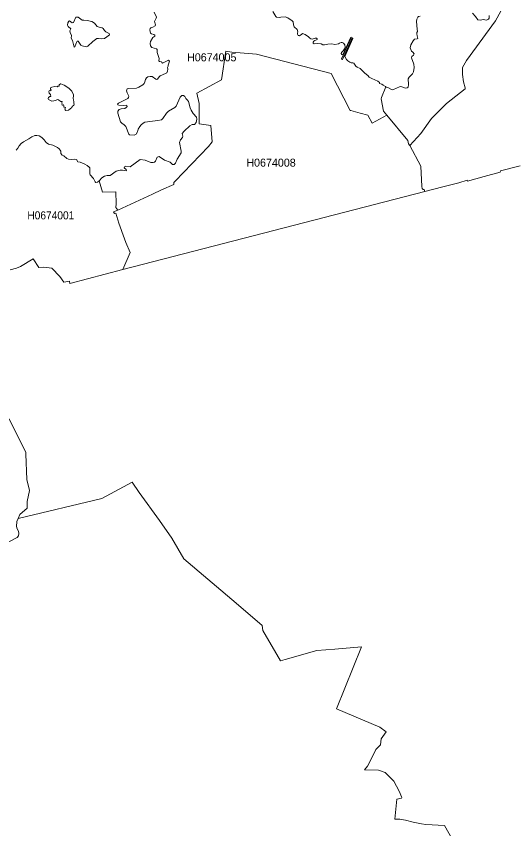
# Model space of a CAD drawing. Extents: x 369010 to 739155, y 6377141 to 6616555.
# Drawn here: x 475314 to 481540, y 6526211 to 6536366 of the extents above; entities that cross this region are included whole.
import ezdxf
from ezdxf.enums import TextEntityAlignment as Align

# ---------------------------------------------------------------- set-up
doc = ezdxf.new("R2010")
doc.units = 0
doc.header["$LTSCALE"] = 40
doc.layers.add('1', color=7, linetype='Continuous', lineweight=13)
doc.layers.add('2', color=7, linetype='Continuous')

msp = doc.modelspace()

# ---------------------------------------------------------------- linework, layer by layer
at = {"layer": '1'}
for points in [[(476200.86, 6536311.81), (476159.48, 6536316.77), (476134.65, 6536315.62), (476105.19, 6536341.6), (476084.84, 6536355.17), (476056.54, 6536355.17), (476028.4, 6536289.63), (476013.67, 6536284), (475978.58, 6536307.67), (475968.49, 6536305.35), (475956.08, 6536285), (475954.92, 6536253.39), (475961.7, 6536237.66), (475994.47, 6536208.2), (475983.22, 6536185.53), (475987.69, 6536164.01), (476002.42, 6536126.78), (475998.94, 6536092.85), (476014.83, 6536062.39), (476037.34, 6535980.97), (476044.12, 6535984.28), (476050.91, 6535994.54), (476064.48, 6536037.4), (476075.9, 6536056.77), (476088.31, 6536055.61), (476119.92, 6536004.63), (476135.65, 6535997.85), (476188.77, 6535985.44), (476209.13, 6535993.38), (476267.89, 6536049.98), (476318.86, 6536088.38), (476340.21, 6536089.54), (476376.46, 6536083.74), (476413.69, 6536088.38), (476446.46, 6536108.74), (476478.08, 6536135.88), (476474.77, 6536151.6), (476430.74, 6536171.96), (476416.01, 6536187.85), (476400.12, 6536212.67), (476385.56, 6536220.62), (476361.73, 6536224.09), (476325.65, 6536237.66), (476289.4, 6536281.69), (476257.79, 6536300.89)], [(476581.52, 6533944.27), (476529.71, 6533920.11), (476539.15, 6533899.42), (476556.36, 6533906.71), (476596.58, 6533780.59), (476666.92, 6533583.48), (476681.98, 6533539.78), (476735.6, 6533414.5), (476646.56, 6533201), (480416.24, 6534176.97), (480410.12, 6534198.99), (480397.21, 6534199.65), (480383.8, 6534211.89), (480378.84, 6534236.39), (480365.43, 6534492.75), (480228.89, 6534750.28), (480211.85, 6534769.97), (480204.4, 6534812.84), (479942.74, 6535127.96), (479757.87, 6535030.81), (479706.4, 6535130.28), (479607.59, 6535154.94), (479492.9, 6535186.55), (479483.63, 6535188.7), (479247.62, 6535651.78), (478314.84, 6535894.41), (478006.5, 6535915.43), (477929.38, 6535930.98), (477877.25, 6535570.02), (477569.08, 6535403.52), (477598.21, 6535273.77), (477598.37, 6535022.53), (477745.01, 6534999.69), (477759.74, 6534797.61), (477712.57, 6534740.35), (477296.33, 6534304.74), (477282.59, 6534287.53), (477280.44, 6534277.77), (477281.93, 6534264.86), (477127.02, 6534196.67), (477013.15, 6534143.04)], [(475959.39, 6535476.84), (475910.4, 6535505.31), (475868.86, 6535520.2), (475864.55, 6535520.04), (475850.15, 6535508.29), (475847.67, 6535493.06), (475831.78, 6535493.72), (475822.68, 6535485.78), (475793.55, 6535487.76), (475757.8, 6535481.97), (475742.08, 6535470.55), (475739.76, 6535461.45), (475740.59, 6535454), (475751.35, 6535441.26), (475745.72, 6535434.31), (475730.99, 6535436.62), (475725.53, 6535432.98), (475720.89, 6535423.71), (475724.7, 6535406.34), (475740.09, 6535389.29), (475743.9, 6535363.14), (475732.31, 6535361.82), (475716.1, 6535351.39), (475711.63, 6535343.28), (475711.46, 6535333.02), (475716.43, 6535325.57), (475757.8, 6535306.54), (475783.29, 6535307.7), (475800.5, 6535312), (475833.44, 6535326.4), (475868.36, 6535300.75), (475886.9, 6535299.92), (475888.22, 6535297.27), (475881.43, 6535288.17), (475880.77, 6535280.06), (475885.9, 6535270.29), (475883.75, 6535262.35), (475886.07, 6535256.89), (475891.86, 6535254.07), (475897.98, 6535258.38), (475902.45, 6535257.71), (475906.92, 6535251.76), (475908.25, 6535235.7), (475913.54, 6535229.08), (475930.42, 6535224.45), (475921.65, 6535206.74), (475923.8, 6535197.31), (475931.75, 6535190.02), (475967.33, 6535193.66), (476007.05, 6535223.79), (476013.67, 6535236.7), (476033.53, 6535252.91), (476038.5, 6535262.35), (476033.53, 6535282.37), (476033.7, 6535302.4), (476027.08, 6535317.79), (476024.43, 6535343.61), (476029.56, 6535371.75), (476027.08, 6535384.82), (476007.55, 6535428.68), (475976.1, 6535463.27)]]:
    msp.add_lwpolyline(points, close=True, dxfattribs=at)
for points in [[(477037.31, 6536418.89), (477065.12, 6536354.51), (477061.97, 6536342.59), (477040.29, 6536301.55), (477052.71, 6536260.01), (477047.41, 6536248.09), (477018.78, 6536227.9), (476993.12, 6536220.78), (476986.5, 6536214.66), (476982.53, 6536196.95), (476991.3, 6536154.58), (477003.22, 6536147.63), (477030.69, 6536138.69), (477042.61, 6536130.75), (477044.26, 6536118.5), (477019.6, 6536099.14), (476991.3, 6536051.8), (476986.01, 6536027.14), (476990.97, 6535995.37), (477008.52, 6535976.5), (477063.63, 6535957.47), (477072.07, 6535949.52), (477073.56, 6535914.6), (477099.87, 6535839.63), (477095.57, 6535810.17), (477102.19, 6535802.22), (477129, 6535797.75), (477132.64, 6535787.16), (477139.59, 6535780.54), (477215.89, 6535815.79), (477225.66, 6535804.7), (477210.27, 6535755.88), (477209.77, 6535740.82), (477202.32, 6535726.26), (477207.95, 6535705.57), (477204.47, 6535678.59), (477193.38, 6535658.4), (477179.32, 6535649.13), (477111.46, 6535623.15), (477096.89, 6535609.91), (477079.19, 6535578.96), (477069.92, 6535574.99), (477057.17, 6535579.45), (477010.01, 6535611.23), (476987, 6535615.2), (476955.22, 6535608.91), (476938.18, 6535596.67), (476926.26, 6535574.99), (476921.3, 6535545.36), (476909.88, 6535525.67), (476894.32, 6535510.77), (476846.16, 6535480.48), (476814.05, 6535465.92)], [(478833.69, 6536125.29), (478826.91, 6536140.68), (478826.08, 6536153.92), (478830.22, 6536169.48), (478823.93, 6536199.76), (478785.2, 6536233.53), (478776.93, 6536258.52), (478772.79, 6536296.75), (478761.2, 6536309.66), (478703.77, 6536346.23), (478673.82, 6536357.49), (478619.37, 6536356.66), (478597.69, 6536352.03), (478564.42, 6536355.83), (478553.66, 6536362.12), (478519.9, 6536425.51)], [(480289.3, 6536078.45), (480271.1, 6536057.1), (480242.3, 6536009.27), (480233.2, 6535970.71), (480248.92, 6535931.15), (480267.62, 6535915.43), (480281.36, 6535897.88), (480276.89, 6535880.51), (480254.38, 6535862.13), (480251.9, 6535844.76), (480279.37, 6535765.65), (480284.83, 6535724.1), (480276.39, 6535670.81), (480263.98, 6535645.49), (480221.11, 6535605.11), (480209.86, 6535582.93), (480212.34, 6535511.43), (480207.05, 6535480.65), (480196.12, 6535472.7), (480176.59, 6535466.08), (480117.18, 6535486.44), (480100.46, 6535484.45), (480024, 6535450.36), (480006.95, 6535447.88), (479953.99, 6535474.03), (479934.96, 6535478.17), (479931.32, 6535482.47), (479931.32, 6535482.47), (479931.32, 6535482.47), (479874.88, 6535352.71), (479872.73, 6535332.85), (479900.7, 6535178.6), (479942.74, 6535127.96), (480204.4, 6534812.84), (480211.85, 6534769.97), (480228.89, 6534750.28), (480365.1, 6534900.89), (480498.83, 6535086.58), (480686.68, 6535276.91), (480920.04, 6535458.14), (480921.69, 6535470.55), (480899.02, 6535547.51), (480885.45, 6535638.21), (480887.76, 6535726.59), (480935.26, 6535814.97), (481299.04, 6536309.99), (481364.75, 6536427.83)], [(480356.66, 6536369.24), (480338.79, 6536363.45), (480327.53, 6536353.02), (480317.93, 6536328.86), (480312.14, 6536300.89), (480322.9, 6536205.72), (480323.4, 6536177.42), (480317.93, 6536165.01), (480316.28, 6536145.31), (480318.93, 6536121.15), (480327.2, 6536089.21), (480321.41, 6536084.24), (480289.3, 6536078.45)], [(481364.75, 6536427.83), (481299.04, 6536309.99), (480935.26, 6535814.97), (480887.76, 6535726.59), (480885.45, 6535638.21), (480899.02, 6535547.51), (480921.69, 6535470.55), (480920.04, 6535458.14), (480686.68, 6535276.91), (480498.83, 6535086.58)], [(481220.26, 6536375.69), (481218.61, 6536341.93), (481211.16, 6536329.19), (481196.1, 6536321.24), (481180.71, 6536318.26), (481149.92, 6536325.05), (481109.21, 6536318.43), (481080.58, 6536323.39), (481050.12, 6536363.78), (481011.56, 6536404.82)], [(476555.7, 6534170.52), (476560.5, 6534020.08), (476559.01, 6533976.05), (476581.52, 6533944.27), (477013.15, 6534143.04), (477127.02, 6534196.67), (477281.93, 6534264.86), (477280.44, 6534277.77), (477282.59, 6534287.53), (477296.33, 6534304.74), (477712.57, 6534740.35), (477759.74, 6534797.61), (477745.01, 6534999.69), (477598.37, 6535022.53), (477598.21, 6535273.77), (477569.08, 6535403.52), (477877.25, 6535570.02), (477929.38, 6535930.98), (478006.5, 6535915.43), (478314.84, 6535894.41), (479247.62, 6535651.78), (479483.63, 6535188.7), (479492.9, 6535186.55), (479607.59, 6535154.94), (479706.4, 6535130.28), (479757.87, 6535030.81), (479942.74, 6535127.96), (479900.7, 6535178.6), (479872.73, 6535332.85), (479874.88, 6535352.71), (479931.32, 6535482.47), (479931.32, 6535482.47), (479931.32, 6535482.47), (479925.69, 6535488.92), (479896.23, 6535503.16), (479880.84, 6535516.07), (479851.71, 6535525.67), (479849.23, 6535536.75), (479828.04, 6535556.45), (479753.57, 6535587.23), (479720.13, 6535606.76), (479702.76, 6535625.96), (479667.34, 6535652.94), (479609.58, 6535713.35), (479573, 6535729.57), (479555.95, 6535744.13), (479528.48, 6535781.04), (479516.89, 6535785.67), (479495.54, 6535785.67), (479478.17, 6535790.64), (479455.99, 6535807.02), (479439.27, 6535827.05), (479417.59, 6535861.14), (479515.9, 6536089.21), (479508.29, 6536095), (479390.28, 6535825.89), (479381.84, 6535824.07), (479377.71, 6535834.16), (479497.2, 6536099.47), (479490.41, 6536103.27), (479391.44, 6535883.65), (479379.86, 6535888.62), (479370.59, 6535901.52), (479376.55, 6535914.77), (479394.75, 6535933.96), (479412.3, 6535959.29), (479421.4, 6535981.79), (479418.92, 6536008.44), (479402.7, 6536028.47), (479383.17, 6536038.4), (479370.59, 6536038.4), (479349.07, 6536030.12), (479337.82, 6536021.68), (479293.3, 6536014.23), (479254.24, 6536022.18), (479203.43, 6536016.72), (479164.7, 6536007.12), (479143.02, 6536008.77), (479121.51, 6536019.53), (479073.67, 6536027.14), (479033.79, 6536023.34), (479022.04, 6536029.96), (479023.36, 6536044.19), (479029.49, 6536053.62), (479042.06, 6536062.39), (479061.92, 6536069.51), (479072.85, 6536077.46), (479072.35, 6536085.73), (479064.9, 6536091.52), (479045.7, 6536091.52), (479010.45, 6536081.59), (478992.58, 6536083.25), (478980.5, 6536090.7), (478963.78, 6536110.72), (478921.41, 6536136.54), (478890.13, 6536148.95), (478879.04, 6536143.99), (478851.57, 6536120.32), (478844.12, 6536124.79), (478833.69, 6536125.29)], [(476814.05, 6535465.92), (476711.27, 6535463.6), (476699.35, 6535457.48), (476690.91, 6535434.47), (476697.2, 6535409.32), (476718.39, 6535369.26), (476715.74, 6535350.23), (476706.8, 6535336.66), (476589.13, 6535278.4), (476576.22, 6535267.31), (476580.69, 6535258.05), (476593.43, 6535255.07), (476651.36, 6535252.42), (476688.27, 6535255.89), (476696.21, 6535251.43), (476697.53, 6535240.01), (476688.27, 6535224.94), (476671.55, 6535214.35), (476625.21, 6535210.88), (476598.4, 6535200.28), (476583.34, 6535180.42), (476580.69, 6535153.45), (476615.94, 6535046.7), (476631, 6535030.48), (476662.78, 6535008.47), (476681.31, 6534988.6), (476717.89, 6534894.1), (476727.16, 6534882.68), (476784.92, 6534880.53), (476810.08, 6534892.45), (476826.79, 6534921.91), (476835.56, 6534956.83), (476856.91, 6534989.27), (476871.97, 6535008.8), (476897.46, 6535028.99), (476919.14, 6535040.9), (477014.31, 6535056.79), (477081.01, 6535062.58), (477129.5, 6535072.18), (477146.22, 6535087.74), (477189.08, 6535153.45), (477214.57, 6535178.6), (477293.18, 6535224.45), (477310.73, 6535242.49), (477362.36, 6535356.69), (477383.05, 6535375.22), (477403.9, 6535374.89), (477417.97, 6535362.48), (477431.71, 6535336.49), (477452.4, 6535316.14), (477463.32, 6535300.75), (477484.17, 6535219.65), (477497.41, 6535193.17), (477524.72, 6535152.45), (477565.77, 6535104.46), (477569.74, 6535078.8), (477559.48, 6535039.25), (477540.94, 6535014.92), (477511.98, 6535014.09), (477480.2, 6534995.06), (477410.86, 6534929.85), (477387.52, 6534902.87), (477395.13, 6534867.12), (477388.18, 6534850.41), (477366.5, 6534819.96), (477353.76, 6534790), (477374.45, 6534681.43), (477373.12, 6534658.92), (477324.13, 6534580.47), (477304.27, 6534528.01), (477287.56, 6534511.62), (477263.72, 6534511.62), (477233.77, 6534540.75), (477166.9, 6534566.07), (477098.88, 6534614.07), (477074.72, 6534606.62), (477053.04, 6534553.33), (477039.8, 6534543.07), (477021.76, 6534538.27), (476995.61, 6534538.76), (476923.78, 6534568.72), (476861.55, 6534574.84), (476735.93, 6534484.98), (476680.32, 6534491.6), (476666.58, 6534485.8), (476661.78, 6534472.56), (476685.12, 6534451.38), (476691.74, 6534434.17), (476638.45, 6534443.1), (476612.3, 6534441.28), (476560.33, 6534430.19), (476486.68, 6534377.73), (476450.93, 6534375.08), (476417.5, 6534365.48), (476381.26, 6534345.62), (476354.77, 6534314.67), (476348.15, 6534308.71), (476348.32, 6534308.22), (476392.51, 6534168.04), (476555.7, 6534170.52)], [(480498.83, 6535086.58), (480365.1, 6534900.89), (480228.89, 6534750.28), (480365.43, 6534492.75), (480378.84, 6534236.39), (480383.8, 6534211.89), (480397.21, 6534199.65), (480410.12, 6534198.99), (480416.24, 6534176.97), (480641.66, 6534235.23), (480843.08, 6534284.22), (480943.54, 6534317.32), (480947.84, 6534305.07), (481156.71, 6534362.17), (481357.8, 6534416.13), (481360.28, 6534432.68), (481608.86, 6534496.4)], [(475239.44, 6533197.02), (475316.24, 6533219.04), (475364.9, 6533237.41), (475525.77, 6533335.05), (475593.46, 6533226.48), (475657.18, 6533231.45), (475756.97, 6533216.06), (475857.27, 6533115.26), (475908.91, 6533043.93), (475978.92, 6533057.01), (475983.88, 6533024.24), (476646.56, 6533201), (476735.6, 6533414.5), (476681.98, 6533539.78), (476666.92, 6533583.48), (476596.58, 6533780.59), (476556.36, 6533906.71), (476539.15, 6533899.42), (476529.71, 6533920.11), (476581.52, 6533944.27), (476559.01, 6533976.05), (476560.5, 6534020.08), (476555.7, 6534170.52), (476392.51, 6534168.04), (476348.32, 6534308.22), (476348.15, 6534308.71), (476327.96, 6534290.51), (476307.61, 6534286.87), (476298.83, 6534296.63), (476280.3, 6534338.01), (476237.1, 6534385.34), (476232.14, 6534395.93), (476230.48, 6534470.41), (476224.19, 6534481.67), (476200.36, 6534501.03), (476170.9, 6534517.91), (476112.64, 6534541.25), (476084.51, 6534545.22), (476065.47, 6534573.85), (476039.49, 6534579.15), (476006.39, 6534577.33), (475966.17, 6534580.47), (475943.33, 6534590.24), (475908.41, 6534620.52), (475888.22, 6534629.46), (475871.83, 6534652.3), (475868.36, 6534677.95), (475860.41, 6534693.84), (475850.65, 6534707.41), (475827.31, 6534726.45), (475771.7, 6534753.75), (475717.09, 6534767.49), (475685.31, 6534790), (475662.31, 6534822.6), (475633.67, 6534852.06), (475601.57, 6534872.42), (475571.11, 6534877.22), (475545.13, 6534877.22), (475508.06, 6534860.5), (475470.16, 6534833.2), (475405.11, 6534797.45), (475373.83, 6534775.44), (475349.17, 6534748.13), (475335.1, 6534716.85), (475310.44, 6534691.19)], [(481608.86, 6534496.4), (481360.28, 6534432.68), (481357.8, 6534416.13), (481156.71, 6534362.17), (480947.84, 6534305.07), (480943.54, 6534317.32), (480843.08, 6534284.22), (480641.66, 6534235.23), (480416.24, 6534176.97), (476646.56, 6533201), (475983.88, 6533024.24), (475978.92, 6533057.01), (475908.91, 6533043.93), (475857.27, 6533115.26), (475756.97, 6533216.06), (475657.18, 6533231.45), (475593.46, 6533226.48), (475525.77, 6533335.05), (475364.9, 6533237.41), (475316.24, 6533219.04), (475239.44, 6533197.02)], [(475222.23, 6529797.24), (475323.85, 6529850.37), (475339.9, 6529872.21), (475347.52, 6529900.68), (475341.89, 6529930.14), (475325.67, 6529958.61), (475318.06, 6529989.06), (475321.04, 6530049.8), (475338.41, 6530089.85), (475359.43, 6530138.01), (475447.65, 6530216.79), (475451.45, 6530299.55), (475479.92, 6530437.24), (475443.84, 6530574.78), (475435.07, 6530894.86), (475432.92, 6530912.9), (475224.38, 6531333.95)], [(475224.38, 6531333.95), (475432.92, 6530912.9), (475435.07, 6530894.86), (475443.84, 6530574.78), (475479.92, 6530437.24), (475451.45, 6530299.55), (475447.65, 6530216.79), (475359.43, 6530138.01), (475338.41, 6530089.85), (476381.42, 6530339.6), (476759.76, 6530543.33), (476846.98, 6530412.58), (477101.36, 6530064.86), (477258.26, 6529842.09), (477405.39, 6529586.72), (478061.95, 6529031.29), (478386.17, 6528749.93), (478393.12, 6528690.52), (478613.41, 6528308.7), (478674.15, 6528327.07), (479067.88, 6528440.6), (479293.13, 6528457.32), (479627.29, 6528485.13), (479314.65, 6527709.08), (479855.52, 6527482.34), (479934.96, 6527423.25), (479871.57, 6527333.38), (479860.98, 6527259.24), (479802.72, 6527201.15), (479748.6, 6527087.44), (479700.44, 6526991.95), (479661.21, 6526947.43), (479838.97, 6526943.79), (479919.57, 6526916.15), (480031.45, 6526807.91), (480095, 6526680.14), (480130.75, 6526601.19), (480125.29, 6526595.4), (480067.86, 6526582.49), (480041.87, 6526332.25), (480102.94, 6526330.93), (480174.77, 6526318.84), (480271.92, 6526294.35), (480376.69, 6526272.34), (480429.98, 6526264.89), (480663.51, 6526252.48), (480768.44, 6526058.84)], [(479919.57, 6526916.15), (479838.97, 6526943.79), (479661.21, 6526947.43), (479700.44, 6526991.95), (479748.6, 6527087.44), (479802.72, 6527201.15), (479860.98, 6527259.24), (479871.57, 6527333.38), (479934.96, 6527423.25), (479855.52, 6527482.34), (479314.65, 6527709.08), (479627.29, 6528485.13), (479293.13, 6528457.32), (479067.88, 6528440.6), (478674.15, 6528327.07), (478613.41, 6528308.7), (478393.12, 6528690.52), (478386.17, 6528749.93), (478061.95, 6529031.29), (477405.39, 6529586.72), (477258.26, 6529842.09), (477101.36, 6530064.86), (476846.98, 6530412.58), (476759.76, 6530543.33), (476381.42, 6530339.6), (475338.41, 6530089.85)], [(475338.41, 6530089.85), (475321.04, 6530049.8), (475318.06, 6529989.06), (475325.67, 6529958.61), (475341.89, 6529930.14), (475347.52, 6529900.68), (475339.9, 6529872.21), (475323.85, 6529850.37), (475222.23, 6529797.24)], [(480768.44, 6526058.84), (480663.51, 6526252.48), (480429.98, 6526264.89), (480376.69, 6526272.34), (480271.92, 6526294.35), (480174.77, 6526318.84), (480102.94, 6526330.93), (480041.87, 6526332.25), (480067.86, 6526582.49), (480125.29, 6526595.4), (480130.75, 6526601.19), (480095, 6526680.14), (480031.45, 6526807.91), (479919.57, 6526916.15)]]:
    msp.add_lwpolyline(points, dxfattribs=at)

# ---------------------------------------------------------------- texts
at = {"layer": '2'}
for s, p in [('H0674005', (477755.02, 6535803.32)), ('H0674008', (478495.6, 6534486.5))]:
    msp.add_text(s, height=100, dxfattribs=at).set_placement(p, align=Align.CENTER)
at = {"layer": '2', "width": 0.95}
msp.add_text('H0674001', height=100, dxfattribs=at).set_placement((475745.29, 6533827.97), align=Align.CENTER)

doc.saveas('drawing.dxf')
